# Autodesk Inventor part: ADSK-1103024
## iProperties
Shininess: 11.0
Length Units: 11272
Angle Units: 11279
Time Units: 11290
Mass Units: 11286
Length Display Precision: 4
Angle Display Precision: 2
Compacted: True
Created: 2000-08
Part Number: ADSK-1103024
Document SubType Name: Modeling
Description: CARB HOUSING
Mass: 7.38977 g
Surface Area: 30.8037 cm^2
Volume: 2.72685 cm^3
Density: 2.71 g/cm^3
Material: Aluminum-6061
Density: 0.0
Volumn: 0.0
Area: 0.0
PropertySet Name: Model Information
Control State: 0
Master: False
Checked Out: False
Author: Autodesk, Inc.
